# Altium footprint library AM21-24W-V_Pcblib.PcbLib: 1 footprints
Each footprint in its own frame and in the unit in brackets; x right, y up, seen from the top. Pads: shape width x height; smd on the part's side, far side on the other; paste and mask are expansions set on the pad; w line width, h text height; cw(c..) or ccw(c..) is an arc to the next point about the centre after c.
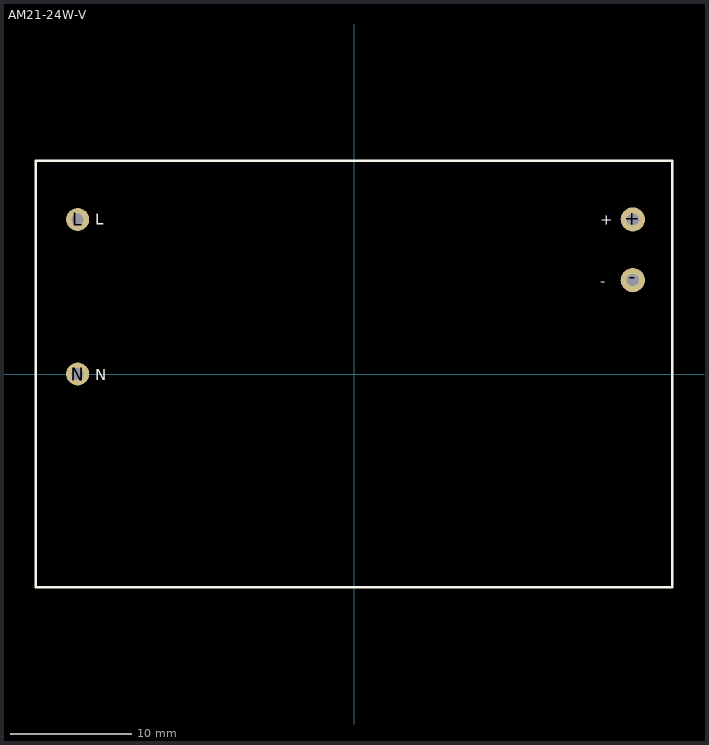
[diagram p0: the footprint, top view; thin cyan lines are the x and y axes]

## AM21-24W-V [mm]
pads (4):
  round 2 hole 1: +(23,12.75) -(23,7.75)
  round 1.9 hole 1: L(-22.8,12.75) N(-22.8,0)
Top Overlay:
  lines w0.2: -26.25,-17.6 -26.25,17.6 26.25,17.6 26.25,-17.6 -26.25,-17.6
  text "-" at 20.32,7.239 h0.9
  text "L" at -21.336,12.319 h0.9
  text "N" at -21.336,-0.508 h0.9
  text "+" at 20.32,12.319 h0.9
